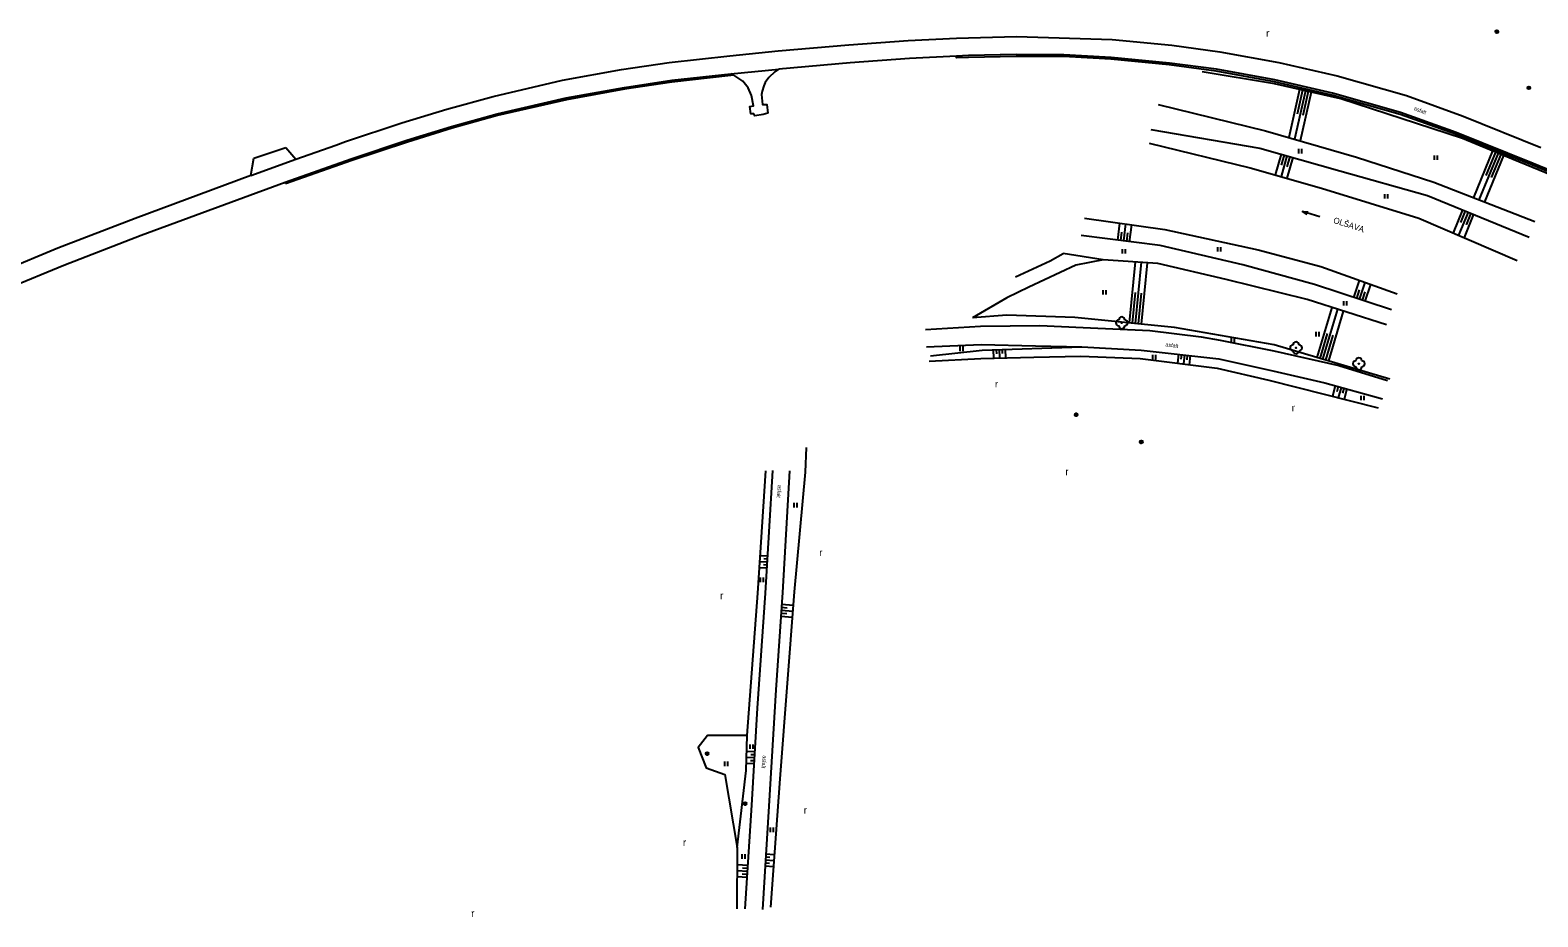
# Model space of a CAD drawing. Extents: x -541281 to -539153, y -1183881 to -1182141.
# Drawn here: x -539932.5 to -539680.5, y -1183148.4 to -1183000.2 of the extents above; entities that cross this region are included whole.
import ezdxf

# ---------------------------------------------------------------- set-up
doc = ezdxf.new("R2010")
doc.units = 0
for name, color, linetype in [('Vrstva 10', 7, 'Continuous'), ('Vrstva 11', 7, 'Continuous'), ('Vrstva 14', 7, 'Continuous'), ('Vrstva 15', 7, 'Continuous'), ('Vrstva 22', 7, 'Continuous'), ('Vrstva 23', 7, 'Continuous'), ('Vrstva 25', 7, 'Continuous'), ('Vrstva 36', 7, 'Continuous'), ('Vrstva 40', 7, 'Continuous'), ('Vrstva 45', 7, 'Continuous')]:
    doc.layers.add(name, color=color, linetype=linetype)

msp = doc.modelspace()

# ---------------------------------------------------------------- linework, layer by layer
at = {"layer": 'Vrstva 10'}
for p, q in [((-539785.76, -1183001.91), (-539777.66, -1183001.52)), ((-539777.66, -1183001.52), (-539775.67, -1183001.44)), ((-539775.67, -1183001.44), (-539767.64, -1183001.25)), ((-539767.64, -1183001.25), (-539751.65, -1183001.74)), ((-539751.65, -1183001.74), (-539741.71, -1183002.67)), ((-539815.55, -1183004.46), (-539807.49, -1183003.66)), ((-539807.49, -1183003.66), (-539795.68, -1183002.64)), ((-539795.68, -1183002.64), (-539785.76, -1183001.91)), ((-539767.68, -1183004.27), (-539775.68, -1183004.42)), ((-539759.77, -1183004.31), (-539767.68, -1183004.27)), ((-539751.85, -1183004.74), (-539759.77, -1183004.31)), ((-539741.71, -1183002.67), (-539733.66, -1183003.79)), ((-539733.66, -1183003.79), (-539723.83, -1183005.59)), ((-539843.49, -1183008.55), (-539833.64, -1183006.78)), ((-539833.64, -1183006.78), (-539825.66, -1183005.58)), ((-539825.66, -1183005.58), (-539815.55, -1183004.46)), ((-539815.39, -1183007.47), (-539807.39, -1183006.68)), ((-539795.46, -1183005.63), (-539807.39, -1183006.68)), ((-539785.51, -1183004.9), (-539795.46, -1183005.63)), ((-539777.67, -1183004.52), (-539785.51, -1183004.9)), ((-539775.68, -1183004.42), (-539777.67, -1183004.52)), ((-539742.09, -1183005.67), (-539751.85, -1183004.74)), ((-539734.22, -1183006.72), (-539742.09, -1183005.67)), ((-539724.49, -1183008.5), (-539734.22, -1183006.72)), ((-539723.83, -1183005.59), (-539714.07, -1183007.81)), ((-539855.12, -1183011.24), (-539843.49, -1183008.55)), ((-539833.17, -1183009.75), (-539825.25, -1183008.55)), ((-539825.25, -1183008.55), (-539815.39, -1183007.47)), ((-539814.87, -1183007.73), (-539815.39, -1183007.47)), ((-539813.36, -1183008.68), (-539814.87, -1183007.73)), ((-539714.86, -1183010.71), (-539724.49, -1183008.5)), ((-539714.07, -1183007.81), (-539702.5, -1183011.12)), ((-539862.82, -1183013.37), (-539855.12, -1183011.24)), ((-539854.43, -1183014.15), (-539842.91, -1183011.49)), ((-539842.91, -1183011.49), (-539833.17, -1183009.75)), ((-539703.47, -1183013.95), (-539714.86, -1183010.71)), ((-539702.5, -1183011.12), (-539693, -1183014.53)), ((-539870.36, -1183015.69), (-539862.82, -1183013.37)), ((-539862.04, -1183016.26), (-539854.43, -1183014.15)), ((-539694.18, -1183017.31), (-539703.47, -1183013.95)), ((-539879.76, -1183018.81), (-539870.36, -1183015.69)), ((-539869.51, -1183018.57), (-539862.04, -1183016.26)), ((-539693, -1183014.53), (-539680.04, -1183019.77)), ((-539888.05, -1183021.73), (-539881.41, -1183019.4)), ((-539881.41, -1183019.4), (-539879.76, -1183018.81)), ((-539878.82, -1183021.69), (-539869.51, -1183018.57)), ((-539681.3, -1183022.49), (-539694.18, -1183017.31)), ((-539895.58, -1183024.46), (-539895.06, -1183021.59)), ((-539895.58, -1183024.46), (-539888.05, -1183021.73)), ((-539895.06, -1183021.59), (-539889.74, -1183019.78)), ((-539889.87, -1183025.58), (-539878.82, -1183021.69)), ((-539889.74, -1183019.78), (-539888.05, -1183021.73)), ((-539895.58, -1183024.46), (-539914.91, -1183031.64)), ((-539664.67, -1183029.27), (-539681.3, -1183022.49)), ((-539913.89, -1183034.45), (-539889.87, -1183025.58)), ((-539914.91, -1183031.64), (-539927.81, -1183036.6)), ((-539926.82, -1183039.44), (-539913.89, -1183034.45)), ((-539927.81, -1183036.6), (-539936.93, -1183040.38)), ((-539936, -1183043.22), (-539926.82, -1183039.44))]:
    msp.add_line(p, q, dxfattribs=at)
for points in [[(-539807.39, -1183006.68), (-539808.03, -1183007.16), (-539809.05, -1183008.12), (-539809.63, -1183008.94), (-539809.88, -1183009.49), (-539810.16, -1183010.39), (-539810.28, -1183010.91), (-539810.12, -1183012.63), (-539809.39, -1183012.59), (-539809.19, -1183014.08)], [(-539809.19, -1183014.08), (-539809.96, -1183014.27), (-539811.37, -1183014.48), (-539811.55, -1183014.18), (-539812.05, -1183014.17), (-539812.21, -1183012.96), (-539811.62, -1183012.85), (-539811.94, -1183011.1), (-539812.47, -1183009.82), (-539813.36, -1183008.68)]]:
    msp.add_lwpolyline(points, dxfattribs=at)
at = {"layer": 'Vrstva 11'}
for p, q in [((-539767.69, -1183004.57), (-539775.69, -1183004.74)), ((-539759.79, -1183004.61), (-539767.69, -1183004.57)), ((-539751.87, -1183005.05), (-539759.79, -1183004.61)), ((-539742.12, -1183005.98), (-539751.87, -1183005.05)), ((-539734.27, -1183007.03), (-539742.12, -1183005.98)), ((-539825.22, -1183008.86), (-539833.14, -1183010.06)), ((-539815.38, -1183007.77), (-539825.22, -1183008.86)), ((-539814.87, -1183007.73), (-539815.38, -1183007.77)), ((-539724.57, -1183008.8), (-539734.27, -1183007.03)), ((-539714.94, -1183011.02), (-539724.57, -1183008.8)), ((-539842.84, -1183011.8), (-539854.35, -1183014.46)), ((-539833.14, -1183010.06), (-539842.84, -1183011.8)), ((-539703.57, -1183014.26), (-539714.94, -1183011.02)), ((-539694.29, -1183017.58), (-539703.57, -1183014.26)), ((-539861.95, -1183016.54), (-539869.42, -1183018.88)), ((-539854.35, -1183014.46), (-539861.95, -1183016.54)), ((-539869.42, -1183018.88), (-539878.73, -1183021.97)), ((-539681.41, -1183022.76), (-539694.29, -1183017.58)), ((-539878.73, -1183021.97), (-539889.77, -1183025.88)), ((-539664.8, -1183029.55), (-539681.41, -1183022.76)), ((-539889.77, -1183025.88), (-539889.87, -1183025.58))]:
    msp.add_line(p, q, dxfattribs=at)
for points in [[(-539775.69, -1183004.74), (-539777.66, -1183004.81), (-539777.67, -1183004.52)], [(-539782.87, -1183050.22), (-539773.66, -1183049.67), (-539763.78, -1183049.56), (-539756.51, -1183049.86), (-539745.37, -1183050.37), (-539736.82, -1183051.44), (-539733.64, -1183051.98), (-539724.65, -1183053.77), (-539713.77, -1183056.24), (-539705.64, -1183058.75)], [(-539782.69, -1183053.08), (-539773.53, -1183052.69), (-539764.46, -1183052.96), (-539756.73, -1183053.09)], [(-539756.73, -1183053.09), (-539746.81, -1183053.64), (-539733.87, -1183055.08), (-539724.8, -1183057.12), (-539716.16, -1183059.13), (-539706.49, -1183061.78)], [(-539812.98, -1183147), (-539811.89, -1183129.69), (-539810.92, -1183113.5), (-539809.59, -1183094.27), (-539808.34, -1183073.74)], [(-539805.57, -1183073.83), (-539806.73, -1183094.13), (-539807.85, -1183110.41), (-539809.04, -1183129.86), (-539810.09, -1183147.11)]]:
    msp.add_lwpolyline(points, dxfattribs=at)
at = {"layer": 'Vrstva 14'}
for points in [[(-539632.14, -1183044.17), (-539658.05, -1183033.42), (-539670.99, -1183027.43), (-539684.68, -1183021.78), (-539693.12, -1183018.31), (-539713.47, -1183011.65), (-539724.52, -1183009.16), (-539736.61, -1183007.15)], [(-539743.98, -1183012.63), (-539726.06, -1183016.99), (-539710.85, -1183021.39), (-539697.9, -1183025.61), (-539681.04, -1183032.15)], [(-539745.23, -1183016.77), (-539726.99, -1183019.88), (-539713.63, -1183023.68), (-539698.99, -1183027.79), (-539682, -1183034.75)], [(-539745.48, -1183019.07), (-539728.6, -1183023.17), (-539716.69, -1183026.58), (-539700.42, -1183031.58), (-539684.02, -1183038.67)], [(-539756.29, -1183031.61), (-539742.86, -1183033.48), (-539727.29, -1183036.91), (-539716.78, -1183039.67), (-539704.03, -1183044.26)], [(-539705.02, -1183046.92), (-539717.85, -1183042.7), (-539729.86, -1183039.37), (-539743.66, -1183036.18), (-539756.82, -1183034.52)], [(-539753.18, -1183038.54), (-539757.73, -1183039.44), (-539765.6, -1183043.11), (-539769.29, -1183044.94), (-539774.99, -1183048.23)], [(-539767.84, -1183041.39), (-539762.05, -1183038.75), (-539759.84, -1183037.51)], [(-539753.18, -1183038.54), (-539759.84, -1183037.51)], [(-539705.85, -1183049.42), (-539719.11, -1183045.17), (-539732.64, -1183041.84), (-539744.05, -1183039.15), (-539753.18, -1183038.54)], [(-539705.28, -1183058.49), (-539724.6, -1183052.76), (-539741.25, -1183049.86), (-539757.88, -1183048.18), (-539769.27, -1183047.8), (-539774.99, -1183048.23)], [(-539782.02, -1183054.63), (-539773.41, -1183053.66), (-539756.73, -1183053.09)], [(-539814.31, -1183136.74), (-539812.83, -1183123.91), (-539812.68, -1183118.07)]]:
    msp.add_lwpolyline(points, dxfattribs=at)
at = {"layer": 'Vrstva 15'}
for p, q in [((-539720.35, -1183010.1), (-539722.16, -1183018.12)), ((-539719.38, -1183010.32), (-539721.2, -1183018.4)), ((-539719.86, -1183010.21), (-539720.77, -1183014.23)), ((-539718.4, -1183010.54), (-539720.24, -1183018.68)), ((-539718.89, -1183010.43), (-539719.8, -1183014.45)), ((-539723.42, -1183020.9), (-539724.41, -1183024.37)), ((-539722.46, -1183021.17), (-539723.45, -1183024.65)), ((-539722.94, -1183021.03), (-539723.43, -1183022.77)), ((-539721.5, -1183021.44), (-539722.49, -1183024.92)), ((-539721.98, -1183021.31), (-539722.47, -1183023.04)), ((-539688.11, -1183020.37), (-539691.31, -1183028.17)), ((-539687.18, -1183020.75), (-539690.38, -1183028.53)), ((-539686.26, -1183021.13), (-539689.45, -1183028.89)), ((-539687.64, -1183020.56), (-539689.24, -1183024.45)), ((-539686.72, -1183020.94), (-539688.32, -1183024.83)), ((-539693.13, -1183030.19), (-539694.71, -1183034.05)), ((-539692.2, -1183030.57), (-539693.79, -1183034.44)), ((-539692.67, -1183030.38), (-539693.46, -1183032.31)), ((-539691.28, -1183030.95), (-539692.87, -1183034.84)), ((-539691.74, -1183030.76), (-539692.53, -1183032.69)), ((-539750.73, -1183035.29), (-539750.37, -1183032.43)), ((-539750.23, -1183035.35), (-539750.06, -1183033.93)), ((-539749.74, -1183035.41), (-539749.38, -1183032.57)), ((-539749.24, -1183035.48), (-539749.06, -1183034.06)), ((-539748.75, -1183035.54), (-539748.39, -1183032.71)), ((-539748.77, -1183049.1), (-539747.74, -1183038.9)), ((-539747.78, -1183049.2), (-539746.74, -1183038.97)), ((-539746.78, -1183049.3), (-539745.74, -1183039.04)), ((-539711.27, -1183044.86), (-539710.33, -1183041.99)), ((-539748.27, -1183049.15), (-539747.75, -1183044.03)), ((-539747.28, -1183049.25), (-539746.76, -1183044.13)), ((-539710.8, -1183045.02), (-539710.33, -1183043.6)), ((-539710.32, -1183045.18), (-539709.39, -1183042.33)), ((-539709.85, -1183045.33), (-539709.38, -1183043.92)), ((-539709.38, -1183045.49), (-539708.45, -1183042.67)), ((-539717.41, -1183054.89), (-539714.92, -1183046.51)), ((-539716.45, -1183055.18), (-539713.97, -1183046.82)), ((-539715.49, -1183055.46), (-539713.02, -1183047.12)), ((-539716.93, -1183055.04), (-539715.69, -1183050.86)), ((-539715.97, -1183055.32), (-539714.73, -1183051.15)), ((-539771.54, -1183053.6), (-539771.49, -1183054.98)), ((-539771.04, -1183053.58), (-539771.02, -1183054.28)), ((-539770.54, -1183053.56), (-539770.49, -1183054.96)), ((-539770.04, -1183053.54), (-539770.02, -1183054.24)), ((-539769.54, -1183053.53), (-539769.49, -1183054.93)), ((-539740.6, -1183054.33), (-539740.76, -1183055.84)), ((-539740.1, -1183054.39), (-539740.18, -1183055.15)), ((-539739.6, -1183054.44), (-539739.77, -1183055.96)), ((-539739.11, -1183054.5), (-539739.19, -1183055.26)), ((-539738.61, -1183054.55), (-539738.78, -1183056.09)), ((-539714.39, -1183059.62), (-539714.86, -1183061.35)), ((-539713.91, -1183059.75), (-539714.14, -1183060.61)), ((-539713.42, -1183059.88), (-539713.89, -1183061.6)), ((-539712.94, -1183060.01), (-539713.18, -1183060.87)), ((-539712.46, -1183060.14), (-539712.92, -1183061.84)), ((-539809.33, -1183090.08), (-539810.58, -1183090.01)), ((-539809.27, -1183089.08), (-539810.51, -1183089.01)), ((-539809.21, -1183088.08), (-539810.45, -1183088.01)), ((-539809.3, -1183089.58), (-539809.92, -1183089.54)), ((-539809.24, -1183088.58), (-539809.86, -1183088.55)), ((-539806.94, -1183097.13), (-539805.04, -1183097.26)), ((-539806.9, -1183096.63), (-539805.96, -1183096.7)), ((-539806.87, -1183096.13), (-539804.96, -1183096.26)), ((-539807, -1183098.13), (-539805.12, -1183098.26)), ((-539806.97, -1183097.63), (-539806.02, -1183097.69)), ((-539811.48, -1183122.8), (-539812.8, -1183122.72)), ((-539811.42, -1183121.8), (-539812.77, -1183121.72)), ((-539811.36, -1183120.8), (-539812.75, -1183120.72)), ((-539811.45, -1183122.3), (-539812.12, -1183122.26)), ((-539811.39, -1183121.3), (-539812.06, -1183121.26)), ((-539809.53, -1183137.84), (-539808.13, -1183137.93)), ((-539812.52, -1183139.76), (-539814.32, -1183139.65)), ((-539812.56, -1183140.26), (-539813.44, -1183140.21)), ((-539809.65, -1183139.84), (-539808.27, -1183139.92)), ((-539809.62, -1183139.34), (-539808.93, -1183139.38)), ((-539809.59, -1183138.84), (-539808.2, -1183138.92)), ((-539809.56, -1183138.34), (-539808.87, -1183138.38)), ((-539812.59, -1183140.76), (-539814.33, -1183140.65)), ((-539812.65, -1183141.76), (-539814.33, -1183141.65)), ((-539812.62, -1183141.26), (-539813.5, -1183141.21))]:
    msp.add_line(p, q, dxfattribs=at)
at = {"layer": 'Vrstva 22'}
for centre in [(-539750.06, -1183049.09), (-539720.94, -1183053.27), (-539710.45, -1183055.93)]:
    msp.add_circle(centre, 0.05, dxfattribs=at)
for centre, start, end in [((-539750.56, -1183049.09), 90, 270), ((-539750.06, -1183048.59), 0, 180), ((-539750.06, -1183049.59), 180, 0), ((-539749.56, -1183049.09), 270, 90), ((-539721.44, -1183053.27), 90, 270), ((-539720.94, -1183052.77), 0, 180), ((-539720.94, -1183053.77), 180, 0), ((-539720.44, -1183053.27), 270, 90), ((-539710.95, -1183055.93), 90, 270), ((-539710.45, -1183055.43), 0, 180), ((-539710.45, -1183056.43), 180, 0), ((-539709.95, -1183055.93), 270, 90)]:
    msp.add_arc(centre, 0.5, start, end, dxfattribs=at)
at = {"layer": 'Vrstva 23'}
for points in [[(-539782.22, -1183055.52), (-539773.59, -1183055.04), (-539764.78, -1183054.8), (-539756.88, -1183054.66), (-539746.97, -1183055.07), (-539734.1, -1183056.67), (-539725.49, -1183058.67), (-539707.22, -1183063.28)], [(-539802.81, -1183069.93), (-539802.95, -1183074.07), (-539804.79, -1183094.06), (-539807.21, -1183125.27), (-539808.77, -1183146.75)], [(-539812.68, -1183118.07), (-539810.86, -1183094.24), (-539809.51, -1183073.8)], [(-539812.68, -1183118.07), (-539819.28, -1183118.03), (-539820.83, -1183120.08), (-539819.49, -1183123.45), (-539816.37, -1183124.58), (-539814.31, -1183136.74)], [(-539814.31, -1183136.74), (-539814.36, -1183147.01)]]:
    msp.add_lwpolyline(points, dxfattribs=at)
at = {"layer": 'Vrstva 25'}
for centre, radius in [((-539687.39, -1183000.43), 0.25), ((-539687.39, -1183000.43), 0.2), ((-539687.39, -1183000.43), 0.15), ((-539687.39, -1183000.43), 0.1), ((-539687.39, -1183000.43), 0.05), ((-539682.03, -1183009.82), 0.25), ((-539682.03, -1183009.82), 0.2), ((-539682.03, -1183009.82), 0.15), ((-539682.03, -1183009.82), 0.1), ((-539682.03, -1183009.82), 0.05), ((-539757.68, -1183064.46), 0.25), ((-539757.68, -1183064.46), 0.2), ((-539757.68, -1183064.46), 0.15), ((-539757.68, -1183064.46), 0.1), ((-539757.68, -1183064.46), 0.05), ((-539746.8, -1183068.98), 0.25), ((-539746.8, -1183068.98), 0.2), ((-539746.8, -1183068.98), 0.15), ((-539746.8, -1183068.98), 0.1), ((-539746.8, -1183068.98), 0.05), ((-539819.35, -1183121.06), 0.25), ((-539819.35, -1183121.06), 0.2), ((-539819.35, -1183121.06), 0.15), ((-539819.35, -1183121.06), 0.1), ((-539819.35, -1183121.06), 0.05), ((-539813, -1183129.42), 0.25), ((-539813, -1183129.42), 0.2), ((-539813, -1183129.42), 0.15), ((-539813, -1183129.42), 0.1), ((-539813, -1183129.42), 0.05)]:
    msp.add_circle(centre, radius, dxfattribs=at)
at = {"layer": 'Vrstva 36'}
for p, q in [((-539720.48, -1183020.79), (-539720.48, -1183020.04)), ((-539719.98, -1183020.79), (-539719.98, -1183020.04)), ((-539697.82, -1183021.85), (-539697.82, -1183021.1)), ((-539697.32, -1183021.85), (-539697.32, -1183021.1)), ((-539706.09, -1183028.34), (-539706.09, -1183027.59)), ((-539705.59, -1183028.34), (-539705.59, -1183027.59)), ((-539749.92, -1183037.53), (-539749.92, -1183036.78)), ((-539749.42, -1183037.53), (-539749.42, -1183036.78)), ((-539734.03, -1183037.17), (-539734.03, -1183036.42)), ((-539733.53, -1183037.17), (-539733.53, -1183036.42)), ((-539753.19, -1183044.38), (-539753.19, -1183043.63)), ((-539752.69, -1183044.38), (-539752.69, -1183043.63)), ((-539712.96, -1183046.22), (-539712.96, -1183045.47)), ((-539712.46, -1183046.22), (-539712.46, -1183045.47)), ((-539731.72, -1183052.38), (-539731.72, -1183051.63)), ((-539731.22, -1183052.38), (-539731.22, -1183051.63)), ((-539717.58, -1183051.35), (-539717.58, -1183050.6)), ((-539717.08, -1183051.35), (-539717.08, -1183050.6)), ((-539777.04, -1183053.81), (-539777.04, -1183053.06)), ((-539776.54, -1183053.81), (-539776.54, -1183053.06)), ((-539744.86, -1183055.21), (-539744.86, -1183054.46)), ((-539744.36, -1183055.21), (-539744.36, -1183054.46)), ((-539710.07, -1183062.03), (-539710.07, -1183061.28)), ((-539709.57, -1183062.03), (-539709.57, -1183061.28)), ((-539804.78, -1183079.94), (-539804.78, -1183079.19)), ((-539804.28, -1183079.94), (-539804.28, -1183079.19)), ((-539810.4, -1183092.4), (-539810.4, -1183091.65)), ((-539809.9, -1183092.4), (-539809.9, -1183091.65)), ((-539812.13, -1183120.3), (-539812.13, -1183119.55)), ((-539811.63, -1183120.3), (-539811.63, -1183119.55)), ((-539816.39, -1183123.16), (-539816.39, -1183122.41)), ((-539815.89, -1183123.16), (-539815.89, -1183122.41)), ((-539808.75, -1183134.19), (-539808.75, -1183133.44)), ((-539808.25, -1183134.19), (-539808.25, -1183133.44)), ((-539813.48, -1183138.64), (-539813.48, -1183137.89)), ((-539812.98, -1183138.64), (-539812.98, -1183137.89))]:
    msp.add_line(p, q, dxfattribs=at)
at = {"layer": 'Vrstva 45'}
msp.add_line((-539716.99, -1183031.39), (-539719.85, -1183030.48), dxfattribs=at)
msp.add_lwpolyline([(-539719.08, -1183030.97), (-539719.85, -1183030.48), (-539718.94, -1183030.53)], dxfattribs=at)

# ---------------------------------------------------------------- texts
at = {"layer": 'Vrstva 36'}
for p in [(-539725.94, -1183001.28), (-539771.25, -1183059.89), (-539721.67, -1183063.89), (-539759.48, -1183074.56), (-539800.62, -1183088.08), (-539817.17, -1183095.27), (-539803.2, -1183131.13), (-539823.39, -1183136.51), (-539858.77, -1183148.36)]:
    msp.add_text('r', height=1.2, dxfattribs=at).set_placement(p)
at = {"layer": 'Vrstva 40'}
for rotation, p in [(337.4304, (-539701.31, -1183013.48)), (351.9514, (-539742.79, -1183053)), (264.6201, (-539807.52, -1183076.16)), (264.6201, (-539810.04, -1183121.35))]:
    msp.add_text('asfalt', height=0.65, rotation=rotation, dxfattribs=at).set_placement(p)
at = {"layer": 'Vrstva 45'}
msp.add_text('OLŠAVA', height=1, rotation=342.1378, dxfattribs=at).set_placement((-539714.81, -1183032.36))

doc.saveas('drawing.dxf')
